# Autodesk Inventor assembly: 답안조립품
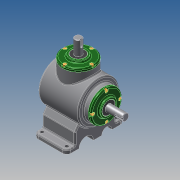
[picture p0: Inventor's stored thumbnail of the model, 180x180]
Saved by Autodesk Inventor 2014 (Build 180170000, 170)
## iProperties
Created: 2018-08
Part Number: 답안조립품
Document SubType Name: Assembly
Designer: kb542
Author: kb542
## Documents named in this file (14)
- C:\Users\kb542\Desktop\480807V1013\답안조립품.iam
- C:\Users\kb542\Desktop\480807V1013\본체.ipt
- C:\Users\kb542\Desktop\480807V1013\메인 베벨기어.ipt
- C:\Users\kb542\Desktop\480807V1013\메인 축.ipt
- 메인 축.ipt
- C:\Users\kb542\Desktop\480807V1013\베어링 6203.ipt
- C:\Users\kb542\Desktop\480807V1013\볼트 M4.ipt
- C:\Users\kb542\Desktop\480807V1013\서브 베벨기어.ipt
- C:\Users\kb542\Desktop\480807V1013\서브 축.ipt
- 서브 축.ipt
- C:\Users\kb542\Desktop\480807V1013\오일실 17 32 8.ipt
- C:\Users\kb542\Desktop\480807V1013\커버.ipt
- C:\Users\kb542\Desktop\480807V1013\키 4x4.ipt
- C:\Users\kb542\Desktop\480807V1013\키 5x5.ipt
